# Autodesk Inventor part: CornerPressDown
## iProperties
Shininess: 64.0
Length Units: 11272
Angle Units: 11279
Time Units: 11290
Mass Units: 11286
Length Display Precision: 3
Angle Display Precision: 2
Compacted: True
Part Number: CornerPressDown
Document SubType Name: Sheet Metal
Created: 2005-12
Designer: Administrator
Manufacturer: Standard
Standards Organization: Custom
Density: 0.0
Volumn: 0.0
Area: 0.0
PropertySet Name: Model Information
Control State: 0
Master: False
Checked Out: False
Author: Administrator
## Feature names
1. Extrusion1
2. Sweep1
3. Extrusion3
4. Extrusion4
5. Plate1
6. Cut1
